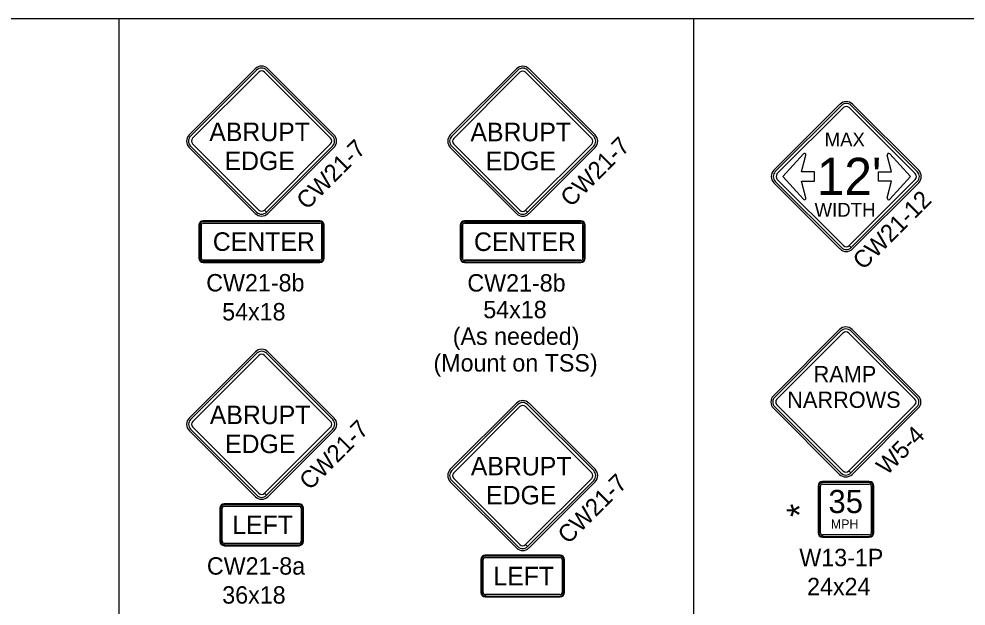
# Model space of a CAD drawing. Extents: x 1458 to 4498, y 17709 to 24109.
# Drawn here: x 2865 to 3682, y 23603 to 24109 of the extents above; entities that cross this region are included whole.
import ezdxf

# ---------------------------------------------------------------- set-up
doc = ezdxf.new("R2010")
doc.units = 0
doc.layers.add('P_ODOT_PLAN_TBlock', color=7, linetype='Continuous')
doc.layers.add('P_TRAF_TCP_General', color=7, linetype='Continuous')

msp = doc.modelspace()

# ---------------------------------------------------------------- linework, layer by layer
at = {"layer": 'P_ODOT_PLAN_TBlock'}
for p, q in [((2951.57, 24109.14), (2951.57, 23153.55)), ((3446.99, 24109.14), (3446.99, 23153.55))]:
    msp.add_line(p, q, dxfattribs=at)
at = {"layer": 'P_TRAF_TCP_General'}
for p, q in [((3069.11, 24066.19), (3012.1, 24009.18)), ((3070.29, 24065.01), (3013.29, 24008)), ((3070.29, 24065.01), (3013.29, 24008)), ((3070.29, 24065.01), (3013.29, 24008)), ((3135.78, 24008), (3078.77, 24065.01)), ((3135.78, 24008), (3078.77, 24065.01)), ((3135.78, 24008), (3078.77, 24065.01)), ((3136.96, 24009.18), (3079.96, 24066.19)), ((3294.24, 24066.08), (3237.23, 24009.08)), ((3295.42, 24064.9), (3238.42, 24007.89)), ((3295.42, 24064.9), (3238.42, 24007.89)), ((3295.42, 24064.9), (3238.42, 24007.89)), ((3360.91, 24007.89), (3303.9, 24064.9)), ((3360.91, 24007.89), (3303.9, 24064.9)), ((3360.91, 24007.89), (3303.9, 24064.9)), ((3362.09, 24009.08), (3305.09, 24066.08)), ((3015.05, 24006.23), (3072.06, 24063.24)), ((3015.05, 24006.23), (3072.06, 24063.24)), ((3077.01, 24063.24), (3134.01, 24006.23)), ((3077.01, 24063.24), (3134.01, 24006.23)), ((3240.18, 24006.13), (3297.19, 24063.13)), ((3240.18, 24006.13), (3297.19, 24063.13)), ((3302.14, 24063.13), (3359.14, 24006.13)), ((3302.14, 24063.13), (3359.14, 24006.13)), ((3573.21, 24035.64), (3516.21, 23978.64)), ((3574.4, 24034.46), (3517.39, 23977.45)), ((3519.16, 23975.69), (3576.16, 24032.69)), ((3581.11, 24032.69), (3638.12, 23975.69)), ((3639.88, 23977.45), (3582.88, 24034.46)), ((3641.07, 23978.64), (3584.06, 24035.64)), ((3012.1, 23998.33), (3069.11, 23941.33)), ((3013.29, 23999.52), (3070.29, 23942.51)), ((3013.29, 23999.52), (3070.29, 23942.51)), ((3013.29, 23999.52), (3070.29, 23942.51)), ((3072.06, 23944.28), (3015.05, 24001.29)), ((3072.06, 23944.28), (3015.05, 24001.29)), ((3134.01, 24001.29), (3077.02, 23944.3)), ((3134.01, 24001.29), (3077.02, 23944.3)), ((3078.77, 23942.51), (3135.78, 23999.52)), ((3078.79, 23942.53), (3135.78, 23999.52)), ((3078.79, 23942.53), (3135.78, 23999.52)), ((3079.96, 23941.33), (3136.96, 23998.33)), ((3238.42, 23999.41), (3295.42, 23942.41)), ((3238.42, 23999.41), (3295.42, 23942.41)), ((3238.42, 23999.41), (3295.42, 23942.41)), ((3297.19, 23944.17), (3240.18, 24001.18)), ((3297.19, 23944.17), (3240.18, 24001.18)), ((3359.14, 24001.18), (3302.15, 23944.19)), ((3359.14, 24001.18), (3302.15, 23944.19)), ((3303.9, 23942.41), (3360.91, 23999.41)), ((3303.92, 23942.42), (3360.91, 23999.41)), ((3303.92, 23942.42), (3360.91, 23999.41)), ((3237.23, 23998.23), (3294.24, 23941.22)), ((3305.09, 23941.22), (3362.09, 23998.23)), ((3543.77, 23991.67), (3543.77, 23991.67)), ((3543.77, 23991.67), (3543.77, 23991.67)), ((3543.77, 23991.67), (3543.77, 23991.67)), ((3613.98, 23991.67), (3613.98, 23991.67)), ((3613.98, 23991.67), (3613.98, 23991.67)), ((3613.98, 23991.67), (3613.98, 23991.67)), ((3516.21, 23967.79), (3573.21, 23910.78)), ((3517.39, 23968.97), (3574.4, 23911.97)), ((3576.16, 23913.73), (3519.16, 23970.74)), ((3638.12, 23970.74), (3581.13, 23913.75)), ((3582.9, 23911.98), (3639.88, 23968.97)), ((3584.06, 23910.78), (3641.07, 23967.79)), ((3078.77, 23942.51), (3077.01, 23944.28)), ((3078.77, 23942.51), (3077.01, 23944.28)), ((3077.02, 23944.3), (3078.79, 23942.53)), ((3077.02, 23944.3), (3078.79, 23942.53)), ((3303.9, 23942.41), (3302.14, 23944.17)), ((3303.9, 23942.41), (3302.14, 23944.17)), ((3302.15, 23944.19), (3303.92, 23942.42)), ((3302.15, 23944.19), (3303.92, 23942.42)), ((3124.76, 23935.08), (3024.3, 23935.08)), ((3124.76, 23934.33), (3024.3, 23934.33)), ((3124.76, 23933.08), (3024.3, 23933.08)), ((3024.3, 23933.08), (3124.76, 23933.08)), ((3349.89, 23934.98), (3249.43, 23934.98)), ((3349.89, 23934.23), (3249.43, 23934.23)), ((3020.55, 23931.34), (3020.55, 23902.85)), ((3021.3, 23931.34), (3021.3, 23902.85)), ((3022.55, 23931.34), (3022.55, 23902.85)), ((3022.55, 23902.85), (3022.55, 23931.34)), ((3126.51, 23902.85), (3126.51, 23931.34)), ((3126.51, 23931.34), (3126.51, 23902.85)), ((3127.76, 23902.85), (3127.76, 23931.34)), ((3128.51, 23902.85), (3128.51, 23931.34)), ((3245.68, 23931.23), (3245.68, 23902.74)), ((3246.43, 23931.23), (3246.43, 23902.74)), ((3247.68, 23931.23), (3247.68, 23902.74)), ((3247.68, 23902.74), (3247.68, 23931.23)), ((3349.89, 23932.98), (3249.43, 23932.98)), ((3249.43, 23932.98), (3349.89, 23932.98)), ((3351.64, 23902.74), (3351.64, 23931.23)), ((3351.64, 23931.23), (3351.64, 23902.74)), ((3352.89, 23902.74), (3352.89, 23931.23)), ((3353.64, 23902.74), (3353.64, 23931.23)), ((3582.88, 23911.97), (3581.11, 23913.73)), ((3582.88, 23911.97), (3581.11, 23913.73)), ((3581.13, 23913.75), (3582.9, 23911.98)), ((3581.13, 23913.75), (3582.9, 23911.98)), ((3024.3, 23901.1), (3124.76, 23901.1)), ((3024.3, 23899.85), (3024.3, 23901.1)), ((3124.76, 23901.1), (3024.32, 23901.1)), ((3024.32, 23901.1), (3024.32, 23899.85)), ((3249.43, 23900.99), (3349.89, 23900.99)), ((3249.43, 23899.74), (3249.43, 23900.99)), ((3349.89, 23900.99), (3249.45, 23900.99)), ((3249.45, 23900.99), (3249.45, 23899.74)), ((3024.3, 23899.1), (3124.76, 23899.1)), ((3024.32, 23899.85), (3124.76, 23899.85)), ((3249.43, 23898.99), (3349.89, 23898.99)), ((3249.45, 23899.74), (3349.89, 23899.74)), ((3572.84, 23841.19), (3515.84, 23784.19)), ((3574.02, 23840.01), (3517.02, 23783)), ((3518.79, 23781.24), (3575.79, 23838.24)), ((3580.74, 23838.24), (3637.74, 23781.24)), ((3639.51, 23783), (3582.51, 23840.01)), ((3640.7, 23784.19), (3583.69, 23841.19)), ((3069.19, 23821.93), (3012.18, 23764.93)), ((3070.37, 23820.75), (3013.37, 23763.74)), ((3070.37, 23820.75), (3013.37, 23763.74)), ((3070.37, 23820.75), (3013.37, 23763.74)), ((3015.13, 23761.98), (3072.14, 23818.98)), ((3015.13, 23761.98), (3072.14, 23818.98)), ((3077.09, 23818.98), (3134.09, 23761.98)), ((3077.09, 23818.98), (3134.09, 23761.98)), ((3135.86, 23763.74), (3078.85, 23820.75)), ((3135.86, 23763.74), (3078.85, 23820.75)), ((3135.86, 23763.74), (3078.85, 23820.75)), ((3137.04, 23764.93), (3080.04, 23821.93)), ((3294.24, 23777.72), (3237.23, 23720.71)), ((3295.42, 23776.53), (3238.42, 23719.53)), ((3295.42, 23776.53), (3238.42, 23719.53)), ((3295.42, 23776.53), (3238.42, 23719.53)), ((3240.18, 23717.76), (3297.19, 23774.77)), ((3240.18, 23717.76), (3297.19, 23774.77)), ((3302.14, 23774.77), (3359.14, 23717.76)), ((3302.14, 23774.77), (3359.14, 23717.76)), ((3360.91, 23719.53), (3303.9, 23776.53)), ((3360.91, 23719.53), (3303.9, 23776.53)), ((3360.91, 23719.53), (3303.9, 23776.53)), ((3362.09, 23720.71), (3305.09, 23777.72)), ((3515.84, 23773.34), (3572.84, 23716.33)), ((3517.02, 23774.52), (3574.02, 23717.52)), ((3575.79, 23719.28), (3518.79, 23776.29)), ((3637.74, 23776.29), (3580.76, 23719.3)), ((3582.52, 23717.53), (3639.51, 23774.52)), ((3583.69, 23716.33), (3640.7, 23773.34)), ((3012.18, 23754.08), (3069.19, 23697.07)), ((3013.37, 23755.26), (3070.37, 23698.26)), ((3013.37, 23755.26), (3070.37, 23698.26)), ((3013.37, 23755.26), (3070.37, 23698.26)), ((3072.14, 23700.02), (3015.13, 23757.03)), ((3072.14, 23700.02), (3015.13, 23757.03)), ((3134.09, 23757.03), (3077.1, 23700.04)), ((3134.09, 23757.03), (3077.1, 23700.04)), ((3078.85, 23698.26), (3135.86, 23755.26)), ((3078.87, 23698.27), (3135.86, 23755.26)), ((3078.87, 23698.27), (3135.86, 23755.26)), ((3080.04, 23697.07), (3137.04, 23754.08)), ((3297.19, 23655.81), (3240.18, 23712.81)), ((3297.19, 23655.81), (3240.18, 23712.81)), ((3359.14, 23712.81), (3302.16, 23655.83)), ((3359.14, 23712.81), (3302.16, 23655.83)), ((3582.51, 23717.52), (3580.74, 23719.28)), ((3582.51, 23717.52), (3580.74, 23719.28)), ((3580.76, 23719.3), (3582.52, 23717.53)), ((3580.76, 23719.3), (3582.52, 23717.53)), ((3237.23, 23709.86), (3294.24, 23652.86)), ((3238.42, 23711.05), (3295.42, 23654.04)), ((3238.42, 23711.05), (3295.42, 23654.04)), ((3238.42, 23711.05), (3295.42, 23654.04)), ((3303.9, 23654.04), (3360.91, 23711.05)), ((3303.92, 23654.06), (3360.91, 23711.05)), ((3303.92, 23654.06), (3360.91, 23711.05)), ((3305.09, 23652.86), (3362.09, 23709.86)), ((3554.28, 23706.29), (3554.28, 23665.9)), ((3555.07, 23706.23), (3555.07, 23665.85)), ((3556.32, 23665.85), (3556.32, 23706.23)), ((3598.46, 23710.09), (3558.07, 23710.09)), ((3598.46, 23709.23), (3558.07, 23709.23)), ((3558.07, 23707.98), (3598.46, 23707.98)), ((3600.21, 23706.23), (3600.21, 23665.85)), ((3601.46, 23665.85), (3601.46, 23706.23)), ((3602.26, 23665.9), (3602.26, 23706.29)), ((3078.85, 23698.26), (3077.09, 23700.02)), ((3078.85, 23698.26), (3077.09, 23700.02)), ((3077.1, 23700.04), (3078.87, 23698.27)), ((3077.1, 23700.04), (3078.87, 23698.27)), ((3106.85, 23690.83), (3042.37, 23690.83)), ((3106.85, 23690.08), (3042.37, 23690.08)), ((3042.37, 23688.83), (3106.85, 23688.83)), ((3038.63, 23687.08), (3038.63, 23658.59)), ((3039.38, 23687.08), (3039.38, 23658.59)), ((3040.63, 23658.59), (3040.63, 23687.08)), ((3108.6, 23687.08), (3108.6, 23658.59)), ((3109.85, 23658.59), (3109.85, 23687.08)), ((3110.6, 23658.59), (3110.6, 23687.08)), ((3558.07, 23662.85), (3558.07, 23664.1)), ((3598.46, 23664.1), (3558.09, 23664.1)), ((3558.09, 23664.1), (3558.09, 23662.85)), ((3042.37, 23655.59), (3042.37, 23656.84)), ((3106.85, 23656.84), (3042.39, 23656.84)), ((3042.39, 23656.84), (3042.39, 23655.59)), ((3042.39, 23655.59), (3106.85, 23655.59)), ((3303.9, 23654.04), (3302.14, 23655.81)), ((3303.9, 23654.04), (3302.14, 23655.81)), ((3302.16, 23655.83), (3303.92, 23654.06)), ((3302.16, 23655.83), (3303.92, 23654.06)), ((3558.07, 23662.11), (3598.46, 23662.11)), ((3558.09, 23662.85), (3598.46, 23662.85)), ((3042.38, 23654.84), (3106.85, 23654.84)), ((3263.68, 23642.86), (3263.68, 23614.38)), ((3264.43, 23642.86), (3264.43, 23614.38)), ((3265.68, 23614.38), (3265.68, 23642.86)), ((3331.9, 23646.61), (3267.43, 23646.61)), ((3331.9, 23645.86), (3267.43, 23645.86)), ((3267.43, 23644.61), (3331.9, 23644.61)), ((3333.65, 23642.86), (3333.65, 23614.38)), ((3334.9, 23614.38), (3334.9, 23642.86)), ((3335.65, 23614.38), (3335.65, 23642.86)), ((3267.43, 23611.38), (3267.43, 23612.63)), ((3267.43, 23610.63), (3331.9, 23610.63)), ((3331.9, 23612.63), (3267.44, 23612.63)), ((3267.44, 23612.63), (3267.44, 23611.38)), ((3267.44, 23611.38), (3331.9, 23611.38))]:
    msp.add_line(p, q, dxfattribs=at)
msp.add_lwpolyline([(4498.44, 24109.14), (1458.44, 24109.14), (1458.44, 22109.14), (4498.44, 22109.14)], close=True, dxfattribs=at)
for points in [[(3541.67, 23992.81), (3523.84, 23973.22), (3541.67, 23953.63)], [(3541.67, 23992.81), (3523.84, 23973.22), (3541.67, 23953.63)], [(3541.67, 23992.81), (3523.84, 23973.22), (3541.67, 23953.63)], [(3543.77, 23954.76), (3540.07, 23969.16), (3551.28, 23969.16), (3551.28, 23977.27), (3540.07, 23977.27), (3543.77, 23991.67)], [(3543.77, 23954.76), (3540.07, 23969.16), (3551.28, 23969.16), (3551.28, 23977.27), (3540.07, 23977.27), (3543.77, 23991.67)], [(3543.77, 23954.76), (3540.07, 23969.16), (3551.28, 23969.16), (3551.28, 23977.27), (3540.07, 23977.27), (3543.77, 23991.67)], [(3613.98, 23954.76), (3617.68, 23969.15), (3606.46, 23969.15), (3606.46, 23977.27), (3617.68, 23977.27), (3613.98, 23991.67)], [(3613.98, 23954.76), (3617.68, 23969.15), (3606.46, 23969.15), (3606.46, 23977.27), (3617.68, 23977.27), (3613.98, 23991.67)], [(3613.98, 23954.76), (3617.68, 23969.15), (3606.46, 23969.15), (3606.46, 23977.27), (3617.68, 23977.27), (3613.98, 23991.67)], [(3616.08, 23992.8), (3633.91, 23973.21), (3616.08, 23953.62)], [(3616.08, 23992.8), (3633.91, 23973.21), (3616.08, 23953.62)], [(3616.08, 23992.8), (3633.91, 23973.21), (3616.08, 23953.62)]]:
    msp.add_lwpolyline(points, dxfattribs=at)
for centre, radius, start, end in [((3074.53, 24060.77), 7.67, 45, 135), ((3074.53, 24060.77), 6, 45, 135), ((3074.53, 24060.77), 6, 45, 135), ((3074.53, 24060.77), 6, 45, 135), ((3074.53, 24060.77), 3.5, 45, 135), ((3074.53, 24060.77), 3.5, 45, 135), ((3299.66, 24060.66), 7.67, 45, 135), ((3299.66, 24060.66), 6, 45, 135), ((3299.66, 24060.66), 6, 45, 135), ((3299.66, 24060.66), 6, 45, 135), ((3299.66, 24060.66), 3.5, 45, 135), ((3299.66, 24060.66), 3.5, 45, 135), ((3578.64, 24030.22), 7.67, 45, 135), ((3578.64, 24030.22), 6, 45, 135), ((3578.64, 24030.22), 3.5, 45, 135), ((3017.53, 24003.76), 7.67, 135, 225), ((3017.53, 24003.76), 6, 135, 225), ((3017.53, 24003.76), 6, 135, 225), ((3017.53, 24003.76), 6, 135, 225), ((3131.54, 24003.76), 6, 315, 45), ((3131.54, 24003.76), 6, 315, 45), ((3131.54, 24003.76), 6, 315, 45), ((3131.54, 24003.76), 7.67, 315, 45), ((3242.66, 24003.65), 7.67, 135, 225), ((3242.66, 24003.65), 6, 135, 225), ((3242.66, 24003.65), 6, 135, 225), ((3242.66, 24003.65), 6, 135, 225), ((3356.67, 24003.65), 6, 315, 45), ((3356.67, 24003.65), 6, 315, 45), ((3356.67, 24003.65), 6, 315, 45), ((3356.67, 24003.65), 7.67, 315, 45), ((3017.53, 24003.76), 3.5, 135, 225), ((3017.53, 24003.76), 3.5, 135, 225), ((3131.54, 24003.76), 3.5, 315, 45), ((3131.54, 24003.76), 3.5, 315, 45), ((3242.66, 24003.65), 3.5, 135, 225), ((3242.66, 24003.65), 3.5, 135, 225), ((3356.67, 24003.65), 3.5, 315, 45), ((3356.67, 24003.65), 3.5, 315, 45), ((3542.58, 23991.98), 1.23, 345.59252, 137.69521), ((3542.58, 23991.98), 1.23, 345.59252, 137.69521), ((3542.58, 23991.98), 1.23, 345.59252, 137.69521), ((3615.17, 23991.97), 1.23, 42.30479, 194.40748), ((3615.17, 23991.97), 1.23, 42.30479, 194.40748), ((3615.17, 23991.97), 1.23, 42.30479, 194.40748), ((3521.63, 23973.21), 7.67, 135, 225), ((3521.63, 23973.21), 6, 135, 225), ((3521.63, 23973.21), 3.5, 135, 225), ((3635.64, 23973.21), 3.5, 315, 45), ((3635.64, 23973.21), 6, 315, 45), ((3635.64, 23973.21), 7.67, 315, 45), ((3542.58, 23954.45), 1.23, 222.30479, 14.40748), ((3542.58, 23954.45), 1.23, 222.30479, 14.40748), ((3542.58, 23954.45), 1.23, 222.30479, 14.40748), ((3615.17, 23954.45), 1.23, 165.59252, 317.69521), ((3615.17, 23954.45), 1.23, 165.59252, 317.69521), ((3615.17, 23954.45), 1.23, 165.59252, 317.69521), ((3074.53, 23946.75), 7.67, 225, 315), ((3074.53, 23946.75), 6, 225, 315), ((3074.53, 23946.75), 6, 225, 315), ((3074.53, 23946.75), 6, 225, 315), ((3074.53, 23946.75), 3.5, 225, 315), ((3074.53, 23946.75), 3.5, 225, 315), ((3299.66, 23946.65), 7.67, 225, 315), ((3299.66, 23946.65), 6, 225, 315), ((3299.66, 23946.65), 6, 225, 315), ((3299.66, 23946.65), 6, 225, 315), ((3299.66, 23946.65), 3.5, 225, 315), ((3299.66, 23946.65), 3.5, 225, 315), ((3024.3, 23931.34), 3.75, 90, 180), ((3024.3, 23931.34), 3, 90, 180), ((3024.3, 23931.34), 1.75, 90, 180), ((3024.3, 23931.34), 1.75, 90, 180), ((3124.76, 23931.34), 3.75, 0, 90), ((3124.76, 23931.34), 3, 0, 90), ((3124.76, 23931.34), 1.75, 0, 90), ((3124.76, 23931.34), 1.75, 0, 90), ((3249.43, 23931.23), 3.75, 90, 180), ((3249.43, 23931.23), 3, 90, 180), ((3349.89, 23931.23), 3.75, 0, 90), ((3349.89, 23931.23), 3, 0, 90), ((3249.43, 23931.23), 1.75, 90, 180), ((3249.43, 23931.23), 1.75, 90, 180), ((3349.89, 23931.23), 1.75, 0, 90), ((3349.89, 23931.23), 1.75, 0, 90), ((3578.64, 23916.21), 7.67, 225, 315), ((3578.64, 23916.21), 6, 225, 315), ((3578.64, 23916.21), 6, 225, 315), ((3578.64, 23916.21), 3.5, 225, 315), ((3024.3, 23902.85), 3.75, 180, 270), ((3024.3, 23902.85), 3, 180, 270), ((3024.3, 23902.85), 1.75, 180, 270), ((3024.3, 23902.85), 1.75, 180, 270), ((3124.76, 23902.85), 1.75, 270, 0), ((3124.76, 23902.85), 3, 270, 0), ((3124.76, 23902.85), 1.75, 270, 0), ((3124.76, 23902.85), 3.75, 270, 0), ((3249.43, 23902.74), 3.75, 180, 270), ((3249.43, 23902.74), 3, 180, 270), ((3249.43, 23902.74), 1.75, 180, 270), ((3249.43, 23902.74), 1.75, 180, 270), ((3349.89, 23902.74), 1.75, 270, 0), ((3349.89, 23902.74), 3, 270, 0), ((3349.89, 23902.74), 1.75, 270, 0), ((3349.89, 23902.74), 3.75, 270, 0), ((3578.27, 23835.77), 7.67, 45, 135), ((3578.27, 23835.77), 6, 45, 135), ((3578.27, 23835.77), 3.5, 45, 135), ((3074.61, 23816.51), 7.67, 45, 135), ((3074.61, 23816.51), 6, 45, 135), ((3074.61, 23816.51), 6, 45, 135), ((3074.61, 23816.51), 6, 45, 135), ((3074.61, 23816.51), 3.5, 45, 135), ((3074.61, 23816.51), 3.5, 45, 135), ((3299.66, 23772.29), 7.67, 45, 135), ((3299.66, 23772.29), 6, 45, 135), ((3299.66, 23772.29), 6, 45, 135), ((3299.66, 23772.29), 6, 45, 135), ((3521.26, 23778.76), 7.67, 135, 225), ((3521.26, 23778.76), 6, 135, 225), ((3521.26, 23778.76), 3.5, 135, 225), ((3635.27, 23778.76), 3.5, 315, 45), ((3635.27, 23778.76), 6, 315, 45), ((3635.27, 23778.76), 7.67, 315, 45), ((3299.66, 23772.29), 3.5, 45, 135), ((3299.66, 23772.29), 3.5, 45, 135), ((3017.61, 23759.5), 7.67, 135, 225), ((3017.61, 23759.5), 6, 135, 225), ((3017.61, 23759.5), 6, 135, 225), ((3017.61, 23759.5), 6, 135, 225), ((3017.61, 23759.5), 3.5, 135, 225), ((3017.61, 23759.5), 3.5, 135, 225), ((3131.62, 23759.5), 3.5, 315, 45), ((3131.62, 23759.5), 3.5, 315, 45), ((3131.62, 23759.5), 6, 315, 45), ((3131.62, 23759.5), 6, 315, 45), ((3131.62, 23759.5), 6, 315, 45), ((3131.62, 23759.5), 7.67, 315, 45), ((3242.66, 23715.29), 7.67, 135, 225), ((3356.67, 23715.29), 7.67, 315, 45), ((3242.66, 23715.29), 6, 135, 225), ((3242.66, 23715.29), 6, 135, 225), ((3242.66, 23715.29), 6, 135, 225), ((3242.66, 23715.29), 3.5, 135, 225), ((3242.66, 23715.29), 3.5, 135, 225), ((3356.67, 23715.29), 3.5, 315, 45), ((3356.67, 23715.29), 3.5, 315, 45), ((3356.67, 23715.29), 6, 315, 45), ((3356.67, 23715.29), 6, 315, 45), ((3356.67, 23715.29), 6, 315, 45), ((3578.27, 23721.76), 7.67, 225, 315), ((3578.27, 23721.76), 6, 225, 315), ((3578.27, 23721.76), 3.5, 225, 315), ((3558.07, 23706.29), 3.8, 90, 180), ((3558.07, 23706.23), 3, 90, 180), ((3558.07, 23706.23), 1.75, 90, 180), ((3598.46, 23706.29), 3.8, 0, 90), ((3598.46, 23706.23), 3, 0, 90), ((3598.46, 23706.23), 1.75, 0, 90), ((3074.61, 23702.5), 7.67, 225, 315), ((3074.61, 23702.5), 6, 225, 315), ((3074.61, 23702.5), 6, 225, 315), ((3074.61, 23702.5), 6, 225, 315), ((3074.61, 23702.5), 3.5, 225, 315), ((3074.61, 23702.5), 3.5, 225, 315), ((3042.37, 23687.08), 3.75, 90, 180), ((3042.37, 23687.08), 3, 90, 180), ((3042.37, 23687.08), 1.75, 90, 180), ((3106.85, 23687.08), 3.75, 0, 90), ((3106.85, 23687.08), 3, 0, 90), ((3106.85, 23687.08), 1.75, 0, 90), ((3558.07, 23665.9), 3.8, 180, 270), ((3558.07, 23665.85), 3, 180, 270), ((3558.07, 23665.85), 1.75, 180, 270), ((3598.46, 23665.9), 3.8, 270, 0), ((3598.46, 23665.85), 3, 270, 0), ((3598.46, 23665.85), 1.75, 270, 0), ((3042.37, 23658.59), 3.75, 180, 270), ((3042.37, 23658.59), 3, 180, 270), ((3042.37, 23658.59), 1.75, 180, 270), ((3106.85, 23658.59), 3, 270, 0), ((3106.85, 23658.59), 1.75, 270, 0), ((3106.85, 23658.59), 3.75, 270, 0), ((3299.66, 23658.28), 3.5, 225, 315), ((3299.66, 23658.28), 3.5, 225, 315), ((3299.66, 23658.28), 7.67, 225, 315), ((3299.66, 23658.28), 6, 225, 315), ((3299.66, 23658.28), 6, 225, 315), ((3299.66, 23658.28), 6, 225, 315), ((3267.43, 23642.86), 3.75, 90, 180), ((3267.43, 23642.86), 3, 90, 180), ((3267.43, 23642.86), 1.75, 90, 180), ((3331.9, 23642.86), 3.75, 0, 90), ((3331.9, 23642.86), 3, 0, 90), ((3331.9, 23642.86), 1.75, 0, 90), ((3267.43, 23614.38), 3.75, 180, 270), ((3267.43, 23614.38), 3, 180, 270), ((3267.43, 23614.38), 1.75, 180, 270), ((3331.9, 23614.38), 3, 270, 0), ((3331.9, 23614.38), 1.75, 270, 0), ((3331.9, 23614.38), 3.75, 270, 0)]:
    msp.add_arc(centre, radius, start, end, dxfattribs=at)

# ---------------------------------------------------------------- texts
for s, height, p in [('ABRUPT', 15.994, (3029.46, 24003.74)), ('ABRUPT', 15.994, (3254.59, 24003.63)), ('EDGE', 15.994, (3042.62, 23978.75)), ('EDGE', 15.994, (3267.75, 23978.64)), ('CENTER', 15.994, (3032.51, 23909.1)), ('CENTER', 15.994, (3257.64, 23909)), ('CW21-8b', 14.994, (3026.82, 23874.11)), ('CW21-8b', 14.994, (3251.95, 23874)), ('54x18', 14.994, (3040.56, 23849.12)), ('54x18', 14.994, (3265.69, 23851.01)), ('(As needed)', 14.994, (3239.35, 23828.02)), ('(Mount on TSS)', 14.994, (3222.75, 23805.03)), ('RAMP', 13.994, (3550.44, 23795.82)), ('NARROWS', 13.994, (3527.72, 23773.7)), ('ABRUPT', 15.994, (3029.89, 23759.65)), ('EDGE', 15.994, (3043.04, 23734.66)), ('ABRUPT', 15.994, (3254.94, 23715.44)), ('EDGE', 15.994, (3268.09, 23690.45)), ('35', 19.992, (3563.27, 23682.94)), ('LEFT', 15.994, (3049.31, 23664.84)), ('MPH', 7.997, (3565.3, 23669.45)), ('W13-1P', 14.994, (3538.15, 23637.12)), ('CW21-8a', 14.994, (3027.39, 23629.85)), ('LEFT', 15.994, (3274.36, 23620.62)), ('24x24', 14.994, (3544.82, 23612.13)), ('36x18', 14.994, (3040.64, 23604.86))]:
    msp.add_text(s, height=height, dxfattribs=at).set_placement(p)
for s, height, rotation, p in [('CW21-7', 14.994, 45, (3341.23, 23946.17)), ('MAX', 11.995, 0.00052, (3559.94, 23999.14)), ('CW21-7', 14.994, 45, (3113.62, 23943.79)), ("12'", 31.987, 0.00052, (3553.17, 23957.36)), ('CW21-12', 14.994, 45, (3593.27, 23891.97)), ('WIDTH', 11.995, 0.00052, (3551.27, 23938.53)), ('CW21-7', 14.994, 45, (3116.08, 23701.92)), ('W5-4', 14.994, 45, (3613.5, 23714.94)), ('CW21-7', 14.994, 45, (3338.9, 23655.47)), ('*', 22.14, 90, (3549.4, 23679.54))]:
    msp.add_text(s, height=height, rotation=rotation, dxfattribs=at).set_placement(p)

doc.saveas('drawing.dxf')
